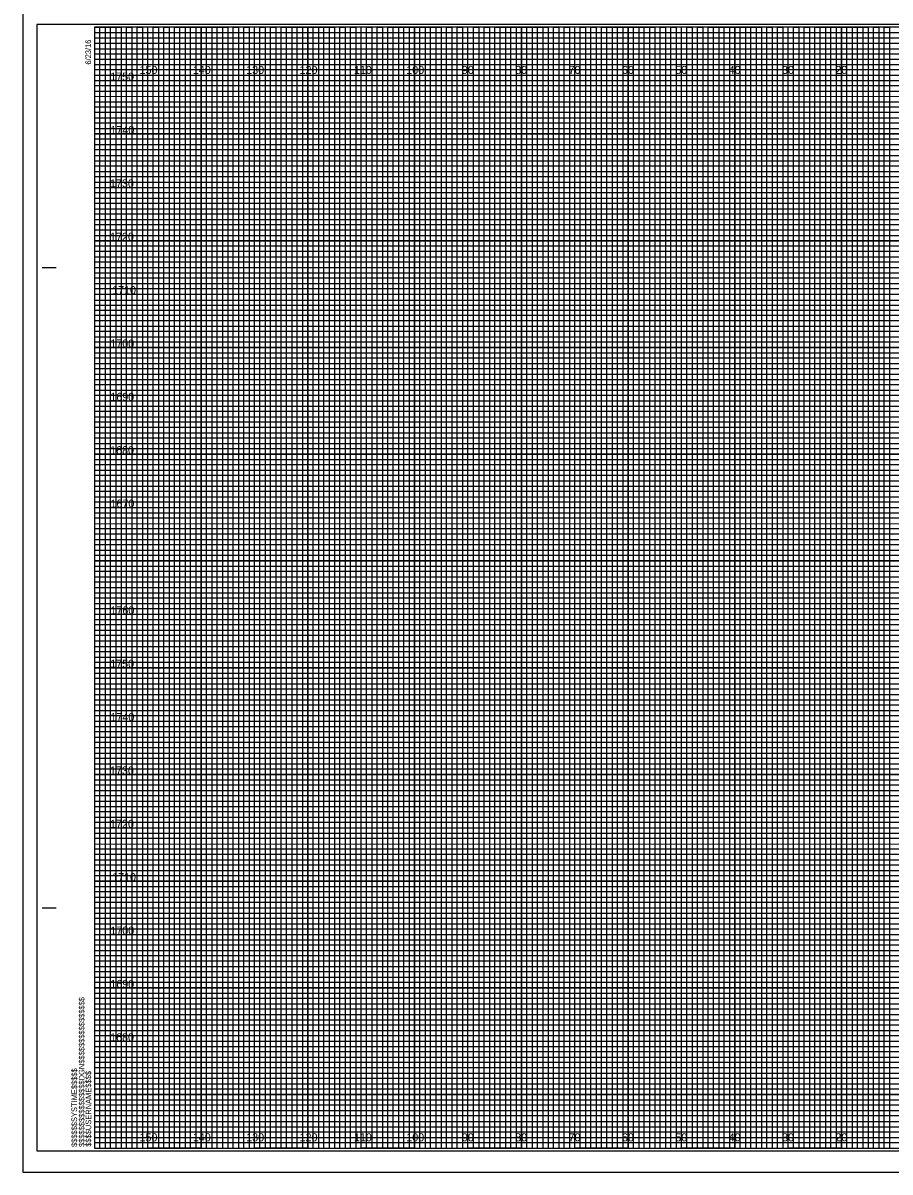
# Model space of a CAD drawing. Extents: x -419 to 4739, y -630 to 13534.
# Drawn here: x 1197.8 to 1360.3, y 419.6 to 634.9 of the extents above; entities that cross this region are included whole.
import ezdxf

# ---------------------------------------------------------------- set-up
doc = ezdxf.new("R2010")
doc.units = 0
for name, color, linetype in [('Old_Level_62', 7, 'Continuous'), ('Pattern 1', 7, 'Continuous'), ('Pattern 18', 7, 'Continuous'), ('Pattern 4', 7, 'Continuous'), ('Pattern 5', 7, 'Continuous'), ('Prop Dimension', 7, 'Continuous'), ('Prop Horizontal Alignment', 7, 'Continuous'), ('Raster_Level_0', 7, 'Continuous'), ('Scratch_Level_0', 7, 'Continuous'), ('Scratch_Level_3', 7, 'Continuous'), ('Scratch_Level_5', 7, 'Continuous')]:
    doc.layers.add(name, color=color, linetype=linetype)

msp = doc.modelspace()

# ---------------------------------------------------------------- linework, layer by layer
at = {"layer": 'Old_Level_62'}
for p, q in [((1201.42, 589.06), (1203.92, 589.06)), ((1201.52, 589.06), (1204.02, 589.06)), ((1201.42, 469.06), (1203.92, 469.06)), ((1201.52, 469.06), (1204.02, 469.06)), ((1211.22, 424.06), (1211.22, 424.06)), ((1211.22, 424.06), (1211.22, 424.06)), ((1211.22, 424.06), (1211.22, 424.06)), ((1211.22, 424.06), (1211.22, 424.06)), ((1211.22, 424.06), (1211.22, 424.06)), ((1211.22, 424.06), (1211.22, 424.06)), ((1211.22, 424.06), (1211.22, 424.06))]:
    msp.add_line(p, q, dxfattribs=at)
msp.add_lwpolyline([(1531.22, 634.06), (1211.22, 634.06), (1211.22, 424.06), (1531.22, 424.06)], close=True, dxfattribs=at)
at = {"layer": 'Pattern 18'}
msp.add_lwpolyline([(1197.82, 419.56), (1534.52, 419.56), (1534.52, 638.56), (1197.82, 638.56)], close=True, dxfattribs=at)
at = {"layer": 'Pattern 4'}
for p, q in [((1211.22, 633.06), (1471.22, 633.06)), ((1471.22, 632.04), (1211.22, 632.04)), ((1211.22, 632.04), (1211.22, 631.06)), ((1211.22, 631.06), (1471.22, 631.06)), ((1471.22, 629.95), (1211.22, 629.95)), ((1211.22, 629.95), (1211.22, 628.06)), ((1211.22, 628.06), (1531.22, 628.06))]:
    msp.add_line(p, q, dxfattribs=at)
for points in [[(1211.22, 627.06), (1481.22, 627.06), (1531.22, 627.06), (1531.22, 626.06), (1211.22, 626.06)], [(1211.22, 625.06), (1531.22, 625.06), (1531.22, 623.06), (1211.22, 623.06)], [(1211.22, 622.06), (1531.22, 622.06), (1531.22, 621.06), (1211.22, 621.04)], [(1211.22, 620.06), (1531.22, 620.06), (1531.22, 618.06), (1211.22, 618.06)], [(1211.22, 617.06), (1531.22, 617.06), (1531.22, 616.06), (1211.22, 616.06)], [(1211.22, 615.06), (1531.22, 615.06), (1531.22, 613.06), (1211.22, 613.06)], [(1211.22, 612.06), (1531.22, 612.06), (1531.22, 611.06), (1211.22, 611.06)], [(1211.22, 610.06), (1531.22, 610.06), (1531.22, 608.06), (1211.22, 608.06)], [(1211.22, 607.06), (1531.22, 607.06), (1531.22, 606.06), (1211.22, 606.06)], [(1211.22, 605.06), (1531.22, 605.06), (1531.22, 603.06), (1211.22, 603.06)], [(1211.22, 602.06), (1531.22, 602.06), (1531.22, 601.06), (1211.22, 601.06)], [(1211.22, 600.06), (1531.22, 600.06), (1531.22, 598.01), (1531.22, 597.06), (1531.22, 596.06), (1211.22, 596.06)], [(1211.22, 598.06), (1531.22, 598.06), (1531.22, 597.06), (1211.22, 597.06)], [(1211.22, 595.06), (1531.22, 595.06), (1531.22, 593.06), (1211.22, 593.09)], [(1211.22, 593.09), (1531.22, 593.06), (1531.22, 592.06), (1211.22, 592.06)], [(1211.22, 591.06), (1531.22, 591.06), (1531.22, 590.06), (1211.22, 590.06)], [(1211.22, 588.06), (1531.22, 588.06), (1531.22, 587.06), (1211.22, 587.06)], [(1211.22, 586.06), (1531.22, 586.06), (1531.22, 585.06), (1211.22, 585.06)], [(1211.15, 582.95), (1531.22, 582.95), (1531.22, 581.94), (1211.15, 581.94)], [(1211.22, 581.06), (1531.22, 581.06), (1531.22, 580.06), (1211.22, 580.06)], [(1211.22, 578.06), (1531.22, 578.06), (1531.22, 577.06), (1211.22, 577.06)], [(1211.22, 576.06), (1531.22, 576.06), (1531.22, 575.06), (1211.22, 575.06)], [(1211.22, 573.06), (1531.22, 573.06), (1531.22, 572.06), (1211.22, 572.06)], [(1211.22, 571.06), (1531.22, 571.06), (1531.22, 570.06), (1211.22, 570.06)], [(1211.22, 568.06), (1531.22, 568.06), (1531.22, 567.06), (1211.22, 567.06)], [(1211.22, 566.06), (1531.22, 566.06), (1531.22, 565.06), (1211.22, 565.06)], [(1211.22, 563.06), (1531.22, 563.06), (1531.21, 562.04), (1211.22, 562.06)], [(1211.22, 561.06), (1531.22, 561.06), (1531.22, 560.06), (1211.22, 560.06)], [(1211.22, 558.06), (1531.22, 558.06), (1531.22, 557.06), (1211.22, 557.06)], [(1211.22, 556.06), (1531.22, 556.06), (1531.22, 555.06), (1211.22, 555.06)], [(1211.22, 553.06), (1531.22, 553.06), (1531.22, 552.06), (1211.22, 552.06)], [(1211.22, 551.06), (1531.22, 551.06), (1531.22, 550.06), (1211.22, 550.06)], [(1211.22, 548.06), (1531.22, 548.06), (1531.22, 547.06), (1211.22, 547.06)], [(1211.22, 546.06), (1531.22, 546.06), (1531.22, 545.06), (1211.22, 545.06)], [(1211.22, 543.06), (1531.22, 543.06), (1531.22, 542.06), (1211.22, 542.06)], [(1211.22, 541.05), (1531.29, 540.97), (1531.22, 540.06), (1211.22, 540.06)], [(1211.22, 538.06), (1531.22, 538.06), (1531.22, 537.06), (1211.22, 537.06)], [(1211.22, 536.06), (1531.22, 536.06), (1531.22, 535.06), (1211.22, 535.06)], [(1211.22, 533.06), (1531.22, 533.06), (1531.22, 532.06), (1211.22, 532.06)], [(1211.22, 531.06), (1531.22, 531.06), (1531.22, 530.06), (1211.22, 530.06)], [(1211.22, 528.06), (1531.22, 528.06), (1531.22, 527.06), (1211.22, 527.06)], [(1211.22, 526.06), (1531.22, 526.06), (1531.22, 525.06), (1211.22, 525.06)], [(1211.22, 523.06), (1531.22, 523.06), (1531.22, 522.06), (1211.22, 522.06)], [(1211.22, 521.06), (1531.22, 521.06), (1531.22, 520.06), (1211.22, 520.06)], [(1211.22, 518.06), (1531.22, 518.06), (1531.22, 517.06), (1211.22, 517.06)], [(1211.22, 516.06), (1531.22, 516.06), (1531.22, 515.06), (1211.22, 515.06)], [(1211.22, 513.06), (1531.22, 513.06), (1531.22, 512.06), (1211.22, 512.06)], [(1211.22, 511.06), (1531.22, 511.06), (1531.22, 510.06), (1211.22, 510.06)], [(1211.22, 508.06), (1531.22, 508.06), (1531.22, 507.06), (1211.22, 507.06)], [(1211.22, 506.06), (1531.22, 506.06), (1531.22, 505.06), (1211.22, 505.06)], [(1211.22, 503.06), (1531.22, 503.06), (1531.21, 502.04), (1211.22, 502.06)], [(1211.22, 501.06), (1531.22, 501.06), (1531.22, 500.06), (1211.22, 500.06)], [(1211.22, 498.06), (1531.22, 498.06), (1531.22, 497.06), (1211.22, 497.06)], [(1211.22, 496.06), (1531.22, 496.06), (1531.22, 495.06), (1211.22, 495.06)], [(1211.22, 493.06), (1531.22, 493.06), (1531.22, 492.06), (1211.22, 492.06)], [(1211.22, 491.06), (1531.22, 491.06), (1531.22, 490.06), (1211.22, 490.06)], [(1211.22, 488.06), (1531.22, 488.06), (1531.22, 487.06), (1211.22, 487.06)], [(1211.22, 486.06), (1531.22, 486.06), (1531.22, 485.06), (1211.22, 485.06)], [(1211.22, 483.06), (1531.22, 483.06), (1531.22, 482.06), (1211.22, 482.06)], [(1211.22, 481.05), (1531.29, 480.97), (1531.22, 480.06), (1211.22, 480.06)], [(1211.22, 478.06), (1531.22, 478.06), (1531.22, 477.06), (1211.22, 477.06)], [(1211.22, 476.06), (1531.22, 476.06), (1531.22, 475.06), (1211.22, 475.06)], [(1211.22, 473.06), (1531.22, 473.06), (1531.22, 472.06), (1211.22, 472.06)], [(1211.22, 471.06), (1531.22, 471.06), (1531.22, 470.06), (1211.22, 470.06)], [(1211.22, 468.06), (1531.22, 468.06), (1531.22, 467.06), (1211.22, 467.06)], [(1211.22, 466.06), (1531.22, 466.06), (1531.22, 465.06), (1211.22, 465.06)], [(1211.22, 463.06), (1531.22, 463.06), (1531.22, 462.06), (1211.22, 462.06)], [(1211.22, 461.06), (1531.22, 461.06), (1531.22, 460.06), (1211.22, 460.06)], [(1211.22, 458.06), (1531.22, 458.06), (1531.22, 457.06), (1211.22, 457.06)], [(1211.22, 456.06), (1531.22, 456.06), (1531.22, 455.06), (1211.22, 455.06)], [(1211.22, 453.06), (1531.22, 453.06), (1531.22, 452.06), (1211.22, 452.06)], [(1211.22, 451.06), (1531.22, 451.06), (1531.22, 450.06), (1211.22, 450.06)], [(1211.22, 448.06), (1531.22, 448.06), (1531.22, 447.06), (1211.22, 447.06)], [(1211.22, 446.06), (1531.22, 446.06), (1531.22, 445.06), (1211.22, 445.06)], [(1211.22, 443.06), (1531.22, 443.06), (1531.22, 442.06), (1211.22, 442.06)], [(1211.22, 441.06), (1531.22, 441.06), (1531.22, 440.06), (1211.22, 440.06)], [(1211.22, 438.06), (1531.22, 438.06), (1531.22, 437.06), (1211.22, 437.06)], [(1211.22, 436.06), (1531.22, 436.06), (1531.22, 435.06), (1211.22, 435.06)], [(1211.22, 433.06), (1531.22, 433.06), (1531.22, 432.06), (1211.22, 432.06)], [(1211.22, 431.06), (1531.22, 431.06), (1531.22, 430.06), (1211.22, 430.06)], [(1211.22, 428.06), (1531.22, 428.06), (1531.22, 427.06), (1211.22, 427.06)], [(1211.22, 426.06), (1531.22, 426.06), (1531.22, 425.06), (1211.22, 425.06)]]:
    msp.add_lwpolyline(points, dxfattribs=at)
at = {"layer": 'Pattern 5'}
for p, q in [((1197.82, 638.56), (1197.82, 419.56)), ((1197.82, 419.56), (1534.52, 419.56))]:
    msp.add_line(p, q, dxfattribs=at)
at = {"layer": 'Prop Dimension'}
for points in [[(1211.22, 424.06), (1212.22, 424.06), (1212.22, 634.06), (1213.22, 634.06), (1213.22, 424.06)], [(1213.22, 424.06), (1214.22, 424.06), (1214.22, 634.06), (1215.22, 634.06), (1215.22, 424.06)], [(1216.22, 424.06), (1217.22, 424.06), (1217.22, 634.06), (1218.22, 634.06), (1218.22, 424.06)], [(1218.22, 424.06), (1219.22, 424.06), (1219.22, 634.06), (1220.22, 634.06), (1220.22, 424.06)], [(1221.22, 424.06), (1222.22, 424.06), (1222.22, 634.06), (1223.22, 634.06), (1223.22, 424.06)], [(1223.22, 424.06), (1224.22, 424.06), (1224.22, 634.06), (1225.22, 634.06), (1225.22, 424.06)], [(1226.22, 424.06), (1227.22, 424.06), (1227.22, 634.06), (1228.22, 634.06), (1228.22, 424.06)], [(1228.22, 424.06), (1229.22, 424.06), (1229.22, 634.06), (1230.22, 634.06), (1230.22, 424.06)], [(1231.22, 424.06), (1232.22, 424.06), (1232.22, 634.06), (1233.22, 634.06), (1233.22, 424.06)], [(1233.22, 424.06), (1234.22, 424.06), (1234.22, 634.06), (1235.22, 634.06), (1235.22, 424.06)], [(1236.22, 424.06), (1237.22, 424.06), (1237.22, 634.06), (1238.22, 634.06), (1238.22, 424.06)], [(1238.22, 424.06), (1239.22, 424.06), (1239.22, 634.06), (1240.22, 634.06), (1240.22, 424.06)], [(1241.22, 424.06), (1242.22, 424.06), (1242.22, 634.06), (1243.22, 634.06), (1243.22, 424.06)], [(1243.22, 424.06), (1244.22, 424.06), (1244.22, 634.06), (1245.22, 634.06), (1245.22, 424.06)], [(1246.22, 424.06), (1247.22, 424.06), (1247.22, 634.06), (1248.22, 634.06), (1248.22, 424.06)], [(1248.22, 424.06), (1249.22, 424.06), (1249.22, 634.06), (1250.22, 634.06), (1250.22, 424.06)], [(1251.22, 424.06), (1252.22, 424.06), (1252.22, 634.06), (1253.22, 634.06), (1253.22, 424.06)], [(1253.22, 424.06), (1254.22, 424.06), (1254.22, 634.06), (1255.22, 634.06), (1255.22, 424.06)], [(1256.22, 424.06), (1257.22, 424.06), (1257.22, 634.06), (1258.22, 634.06), (1258.22, 424.06)], [(1258.22, 424.06), (1259.22, 424.06), (1259.22, 634.06), (1260.22, 634.06), (1260.22, 424.06)], [(1261.22, 424.06), (1262.22, 424.06), (1262.22, 634.06), (1263.22, 634.06), (1263.22, 424.06)], [(1263.22, 424.06), (1264.22, 424.06), (1264.22, 634.06), (1265.22, 634.06), (1265.22, 424.06)], [(1266.22, 424.06), (1267.22, 424.06), (1267.22, 634.06), (1268.22, 634.06), (1268.22, 424.06)], [(1268.22, 424.06), (1269.22, 424.06), (1269.22, 634.06), (1270.22, 634.06), (1270.22, 424.06)], [(1271.22, 424.06), (1272.22, 424.06), (1272.22, 634.06), (1273.22, 634.06), (1273.22, 424.06)], [(1273.22, 424.06), (1274.22, 424.06), (1274.22, 634.06), (1275.22, 634.06), (1275.22, 424.06)], [(1276.22, 424.06), (1277.22, 424.06), (1277.22, 634.06), (1278.22, 634.06), (1278.22, 424.06)], [(1278.22, 424.06), (1279.22, 424.06), (1279.22, 634.06), (1280.22, 634.06), (1280.22, 424.06)], [(1281.22, 424.06), (1282.22, 424.06), (1282.22, 634.06), (1283.22, 634.06), (1283.22, 424.06)], [(1283.22, 424.06), (1284.22, 424.06), (1284.22, 634.06), (1285.22, 634.06), (1285.22, 424.06)], [(1286.22, 424.06), (1287.22, 424.06), (1287.22, 634.06), (1288.22, 634.06), (1288.22, 424.06)], [(1288.22, 424.06), (1289.22, 424.06), (1289.22, 634.06), (1290.22, 634.06), (1290.22, 424.06)], [(1291.22, 424.06), (1292.22, 424.06), (1292.22, 634.06), (1293.22, 634.06), (1293.22, 424.06)], [(1293.22, 424.06), (1294.22, 424.06), (1294.22, 634.06), (1295.22, 634.06), (1295.22, 424.06)], [(1296.22, 424.06), (1297.22, 424.06), (1297.22, 634.06), (1298.22, 634.06), (1298.22, 424.06)], [(1298.22, 424.06), (1299.22, 424.06), (1299.22, 634.06), (1300.22, 634.06), (1300.22, 424.06)], [(1301.22, 424.06), (1302.22, 424.06), (1302.22, 634.06), (1303.22, 634.06), (1303.22, 424.06)], [(1303.22, 424.06), (1304.22, 424.06), (1304.22, 634.06), (1305.22, 634.06), (1305.22, 424.06)], [(1306.22, 424.06), (1307.22, 424.06), (1307.22, 634.06), (1308.22, 634.06), (1308.22, 424.06)], [(1308.22, 424.06), (1309.22, 424.06), (1309.22, 634.06), (1310.22, 634.06), (1310.22, 424.06)], [(1311.22, 424.06), (1312.22, 424.06), (1312.22, 634.06), (1313.22, 634.06), (1313.22, 424.06)], [(1313.22, 424.06), (1314.22, 424.06), (1314.22, 634.06), (1315.22, 634.06), (1315.22, 424.06)], [(1316.22, 424.06), (1317.22, 424.06), (1317.22, 634.06), (1318.22, 634.06), (1318.22, 424.06)], [(1318.22, 424.06), (1319.22, 424.06), (1319.22, 634.06), (1320.22, 634.06), (1320.22, 424.06)], [(1321.22, 424.06), (1322.22, 424.06), (1322.22, 634.06), (1323.22, 634.06), (1323.22, 424.06)], [(1323.22, 424.06), (1324.22, 424.06), (1324.22, 634.06), (1325.22, 634.06), (1325.22, 424.06)], [(1326.22, 424.06), (1327.22, 424.06), (1327.22, 634.06), (1328.22, 634.06), (1328.22, 424.06)], [(1328.22, 424.06), (1329.22, 424.06), (1329.22, 634.06), (1330.22, 634.06), (1330.22, 424.06)], [(1331.22, 424.06), (1332.22, 424.06), (1332.22, 634.06), (1333.22, 634.06), (1333.22, 424.06)], [(1333.22, 424.06), (1334.22, 424.06), (1334.22, 634.06), (1335.22, 634.06), (1335.22, 424.06)], [(1336.22, 424.06), (1337.22, 424.06), (1337.22, 634.06), (1338.22, 634.06), (1338.22, 424.06)], [(1338.22, 424.06), (1339.22, 424.06), (1339.22, 634.06), (1340.22, 634.06), (1340.22, 424.06)], [(1341.22, 424.06), (1342.22, 424.06), (1342.22, 634.06), (1343.22, 634.06), (1343.22, 424.06)], [(1343.22, 424.06), (1344.22, 424.06), (1344.22, 634.06), (1345.22, 634.06), (1345.22, 424.06)], [(1346.22, 424.06), (1347.22, 424.06), (1347.22, 634.06), (1348.22, 634.06), (1348.22, 424.06)], [(1348.22, 424.06), (1349.22, 424.06), (1349.22, 634.06), (1350.22, 634.06), (1350.22, 424.06)], [(1351.22, 424.06), (1352.22, 424.06), (1352.22, 634.06), (1353.22, 634.06), (1353.22, 424.06)], [(1353.22, 424.06), (1354.22, 424.06), (1354.22, 634.06), (1355.22, 634.06), (1355.22, 424.06)], [(1356.22, 424.06), (1357.22, 424.06), (1357.22, 634.06), (1358.22, 634.06), (1358.22, 424.06)], [(1358.22, 424.06), (1359.22, 424.06), (1359.22, 634.06), (1360.22, 634.06), (1360.22, 424.06)]]:
    msp.add_lwpolyline(points, dxfattribs=at)
at = {"layer": 'Prop Horizontal Alignment'}
for points in [[(1211.22, 634.06), (1216.22, 634.06), (1216.22, 424.06), (1226.22, 424.06), (1226.22, 634.06), (1236.22, 634.06), (1236.22, 424.06), (1246.22, 424.06), (1246.22, 634.06), (1256.22, 634.06), (1256.22, 424.06), (1266.22, 424.06), (1266.22, 634.06), (1276.22, 634.06), (1276.22, 424.06), (1286.22, 424.06), (1286.22, 634.06), (1296.22, 634.06), (1296.22, 424.06), (1306.22, 424.06), (1306.22, 634.06), (1316.22, 634.06), (1316.22, 424.06), (1326.22, 424.06), (1326.22, 634.06), (1336.22, 634.06), (1336.22, 424.06), (1346.22, 424.06), (1346.22, 634.06), (1356.22, 634.06), (1356.22, 424.06), (1366.22, 424.06)], [(1211.22, 629.06), (1486.22, 629.06)], [(1211.22, 609.06), (1531.22, 609.06), (1531.22, 619.06), (1211.22, 619.06)], [(1211.22, 589.06), (1531.22, 589.06), (1531.22, 599.06), (1211.22, 599.06)], [(1211.22, 569.06), (1531.22, 569.06), (1531.22, 579.06), (1211.22, 579.06)], [(1211.22, 549.06), (1531.22, 549.06), (1531.22, 559.06), (1211.22, 559.06)], [(1211.22, 529.06), (1531.22, 529.06), (1531.22, 539.06), (1211.22, 539.06)], [(1211.22, 509.06), (1531.22, 509.06), (1531.22, 519.06), (1211.22, 519.06)], [(1211.22, 489.06), (1531.22, 489.06), (1531.22, 499.06), (1211.22, 499.06)], [(1211.22, 469.06), (1531.22, 469.06), (1531.22, 479.06), (1211.22, 479.06)], [(1211.22, 449.06), (1531.22, 449.06), (1531.22, 459.06), (1211.22, 459.06)], [(1211.22, 429.06), (1531.22, 429.06), (1531.22, 439.06), (1211.22, 439.06)]]:
    msp.add_lwpolyline(points, dxfattribs=at)
at = {"layer": 'Scratch_Level_0'}
for p, q in [((1221.22, 424.06), (1221.22, 634.06)), ((1231.22, 424.06), (1231.22, 634.06)), ((1241.22, 424.06), (1241.22, 634.06)), ((1251.22, 424.06), (1251.22, 634.06)), ((1261.22, 424.06), (1261.22, 634.06)), ((1271.22, 424.06), (1271.22, 634.06)), ((1281.22, 424.06), (1281.22, 634.06)), ((1291.22, 424.06), (1291.22, 634.06)), ((1301.22, 424.06), (1301.22, 634.06)), ((1311.22, 424.06), (1311.22, 634.06)), ((1321.22, 424.06), (1321.22, 634.06)), ((1331.22, 424.06), (1331.22, 634.06)), ((1341.22, 424.06), (1341.22, 634.06)), ((1351.22, 424.06), (1351.22, 634.06)), ((1211.22, 624.06), (1531.22, 624.06)), ((1211.22, 614.06), (1531.22, 614.06)), ((1211.22, 604.06), (1531.22, 604.06)), ((1211.22, 594.06), (1531.22, 594.06)), ((1211.22, 584.06), (1531.22, 584.06)), ((1211.22, 574.06), (1531.22, 574.06)), ((1211.22, 564.06), (1531.22, 564.06)), ((1211.22, 554.06), (1531.22, 554.06)), ((1211.22, 544.06), (1531.22, 544.06)), ((1211.22, 534.06), (1531.22, 534.06)), ((1211.22, 524.06), (1531.22, 524.06)), ((1211.22, 514.06), (1531.22, 514.06)), ((1211.22, 504.06), (1531.22, 504.06)), ((1211.22, 494.06), (1531.22, 494.06)), ((1211.22, 484.06), (1531.22, 484.06)), ((1211.22, 474.06), (1531.22, 474.06)), ((1211.22, 464.06), (1531.22, 464.06)), ((1211.22, 454.06), (1531.22, 454.06)), ((1211.22, 444.06), (1531.22, 444.06)), ((1211.22, 434.06), (1531.22, 434.06))]:
    msp.add_line(p, q, dxfattribs=at)
at = {"layer": 'Scratch_Level_3'}
for p, q in [((1221.22, 634.06), (1211.22, 634.06)), ((1221.22, 424.06), (1221.22, 634.06)), ((1241.22, 634.06), (1231.22, 634.06)), ((1231.22, 634.06), (1231.22, 424.06)), ((1241.22, 424.06), (1241.22, 634.06)), ((1261.22, 634.06), (1251.22, 634.06)), ((1251.22, 634.06), (1251.22, 424.06)), ((1261.22, 424.06), (1261.22, 634.06)), ((1281.22, 634.06), (1271.22, 634.06)), ((1271.22, 634.06), (1271.22, 424.06)), ((1281.22, 424.06), (1281.22, 634.06)), ((1301.22, 634.06), (1291.22, 634.06)), ((1291.22, 634.06), (1291.22, 424.06)), ((1301.22, 424.06), (1301.22, 634.06)), ((1321.22, 634.06), (1311.22, 634.06)), ((1311.22, 634.06), (1311.22, 424.06)), ((1321.22, 424.06), (1321.22, 634.06)), ((1341.22, 634.06), (1331.22, 634.06)), ((1331.22, 634.06), (1331.22, 424.06)), ((1341.22, 424.06), (1341.22, 634.06)), ((1361.22, 634.06), (1351.22, 634.06)), ((1351.22, 634.06), (1351.22, 424.06)), ((1231.22, 424.06), (1221.22, 424.06)), ((1251.22, 424.06), (1241.22, 424.06)), ((1271.22, 424.06), (1261.22, 424.06)), ((1291.22, 424.06), (1281.22, 424.06)), ((1311.22, 424.06), (1301.22, 424.06)), ((1331.22, 424.06), (1321.22, 424.06)), ((1351.22, 424.06), (1341.22, 424.06))]:
    msp.add_line(p, q, dxfattribs=at)
for points in [[(1211.22, 624.06), (1531.22, 624.06), (1531.22, 614.06), (1211.22, 614.06)], [(1211.22, 604.06), (1531.22, 604.06), (1531.22, 594.06), (1211.22, 594.06)], [(1211.22, 584.06), (1531.22, 584.06), (1531.22, 574.06), (1211.22, 574.06)], [(1211.22, 564.06), (1531.22, 564.06), (1531.22, 554.06), (1211.22, 554.06)], [(1211.22, 544.06), (1531.22, 544.06), (1531.22, 534.06), (1211.22, 534.06)], [(1211.22, 524.06), (1531.22, 524.06), (1531.22, 514.06), (1211.22, 514.06)], [(1211.22, 504.06), (1531.22, 504.06), (1531.22, 494.06), (1211.22, 494.06)], [(1211.22, 484.06), (1531.22, 484.06), (1531.22, 474.06), (1211.22, 474.06)], [(1211.22, 464.06), (1531.22, 464.06), (1531.22, 454.06), (1211.22, 454.06)], [(1211.22, 444.06), (1531.22, 444.06), (1531.22, 434.06), (1211.22, 434.06)]]:
    msp.add_lwpolyline(points, dxfattribs=at)
at = {"layer": 'Scratch_Level_5'}
msp.add_lwpolyline([(1200.42, 423.56), (1533.62, 423.56), (1533.62, 634.56), (1200.42, 634.56)], close=True, dxfattribs=at)

# ---------------------------------------------------------------- texts
at = {"layer": 'Old_Level_62'}
for s, p in [('6/23/16', (1210.57, 627.06)), ('$$$$$$$$$$$$$$$$DGN$$$$$$$$$$$$$$$$', (1209.34, 424.24)), ('$$$$$$SYSTIME$$$$$', (1207.96, 424.24)), ('$$$$USERNAME$$$$', (1210.6, 424.29))]:
    msp.add_text(s, height=1.05, rotation=90, dxfattribs=at).set_placement(p)
at = {"layer": 'Pattern 1'}
for s, p in [('1750', (1214.17, 624.06)), ('1740', (1214.22, 614.06)), ('1730', (1214.14, 604.06)), ('1720', (1214.15, 594.06)), ('1710', (1214.53, 584.06)), ('1700', (1214.2, 574.06)), ('1690', (1214.19, 564.06)), ('1680', (1214.16, 554.06)), ('1670', (1214.22, 544.06)), ('1760', (1214.22, 524.06)), ('1750', (1214.17, 514.06)), ('1740', (1214.22, 504.06)), ('1730', (1214.14, 494.06)), ('1720', (1214.15, 484.06)), ('1710', (1214.53, 474.06)), ('1700', (1214.2, 464.06)), ('1690', (1214.19, 454.06)), ('1680', (1214.16, 444.06))]:
    msp.add_text(s, height=1.5, dxfattribs=at).set_placement(p)
at = {"layer": 'Raster_Level_0'}
for s, p in [('150', (1219.66, 625.31)), ('140', (1229.66, 625.31)), ('130', (1239.66, 625.31)), ('120', (1249.66, 625.31)), ('110', (1259.84, 625.31)), ('100', (1269.66, 625.31)), ('90', (1280.08, 625.31)), ('80', (1290.08, 625.31)), ('70', (1300.08, 625.31)), ('60', (1310.08, 625.31)), ('50', (1320.08, 625.31)), ('40', (1330.08, 625.31)), ('30', (1340.08, 625.31)), ('20', (1350.08, 625.31)), ('150', (1219.66, 425.31)), ('140', (1229.66, 425.31)), ('130', (1239.66, 425.31)), ('120', (1249.66, 425.31)), ('110', (1259.84, 425.31)), ('100', (1269.66, 425.31)), ('90', (1280.08, 425.31)), ('80', (1290.08, 425.31)), ('70', (1300.08, 425.31)), ('60', (1310.08, 425.31)), ('50', (1320.08, 425.31)), ('40', (1330.08, 425.31)), ('30', (1340.08, 425.31)), ('20', (1350.08, 425.31))]:
    msp.add_text(s, height=1.5, dxfattribs=at).set_placement(p)

doc.saveas('drawing.dxf')
